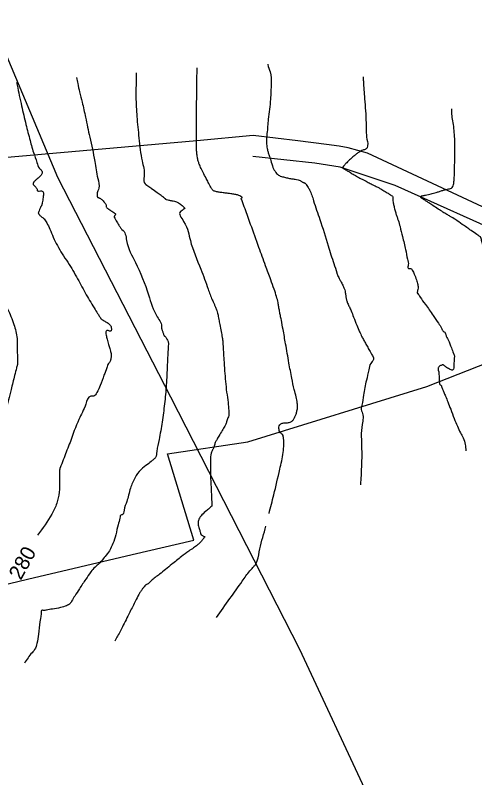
# Model space of a CAD drawing. Extents: x -478232 to -472707, y -1118753 to -1113967.
# Drawn here: x -476973 to -476849.1, y -1116433.2 to -1116227.8 of the extents above; entities that cross this region are included whole.
import ezdxf

# ---------------------------------------------------------------- set-up
doc = ezdxf.new("R2010")
doc.units = 0
for name, color, linetype in [('cestní_příkop', 7, 'Continuous'), ('ObPÚ', 7, 'Continuous'), ('plyn_vtl', 7, 'Continuous'), ('Vrstevnice_hlavni', 7, 'Continuous'), ('Vrstevnice_popis', 7, 'Continuous'), ('Vrstevnice_vedlejsi', 7, 'Continuous')]:
    doc.layers.add(name, color=color, linetype=linetype)

msp = doc.modelspace()

# ---------------------------------------------------------------- linework, layer by layer
at = {"layer": 'cestní_příkop'}
msp.add_lwpolyline([(-476811.35, -1116300.528), (-476838.09, -1116288.27), (-476870.56, -1116273.66), (-476885.39, -1116268.71), (-476892.25, -1116267.66), (-476908.96, -1116265.87)], dxfattribs=at)
at = {"layer": 'ObPÚ'}
msp.add_lwpolyline([(-477024.71, -1116392.97), (-476969.66, -1116379.77), (-476941.47, -1116373.14), (-476924.87, -1116369.24), (-476931.96, -1116345.98), (-476910.26, -1116342.76), (-476862.03, -1116327.86), (-476806.79, -1116306.12), (-476811.56, -1116301.96), (-476807.61, -1116297.99), (-476845.68, -1116280.05), (-476877.99, -1116264.97), (-476883.21, -1116263.56), (-476885.7, -1116263.12), (-476889.08, -1116262.59), (-476896.84, -1116261.69), (-476908.87, -1116260.23), (-476924.05, -1116261.64), (-477007.86, -1116269.03)], dxfattribs=at)
at = {"layer": 'plyn_vtl'}
msp.add_lwpolyline([(-476807.539, -1117641.044), (-476845.2, -1117492.76), (-476870.94, -1117395.8), (-476871.43, -1117390.49), (-476872.65, -1117388.81), (-476881.04, -1117350.81), (-476885.089, -1117338.623), (-476885.25, -1117338.15), (-476884.46, -1117337.68), (-476892.45, -1117313.5), (-476884.4, -1117251.02), (-476853.71, -1117059.16), (-476824.27, -1116852.24), (-476807.41, -1116714.75), (-476840.86, -1116589.24), (-476878.96, -1116446.19), (-476877.5, -1116438.9), (-476896.24, -1116398.66), (-476931.01, -1116330.67), (-476961.52, -1116271.51), (-476999.07, -1116182.23)], dxfattribs=at)
at = {"layer": 'Vrstevnice_hlavni'}
for points in [[(-476972.63, -1116245.946), (-476971.435, -1116251.566), (-476970.258, -1116256.657), (-476969.13, -1116261.058), (-476968.053, -1116264.769), (-476967.147, -1116267.447), (-476966.415, -1116269.092), (-476965.854, -1116269.706), (-476965.77, -1116270.372), (-476966.163, -1116271.09), (-476967.034, -1116271.861), (-476967.635, -1116272.399), (-476967.969, -1116272.704), (-476968.034, -1116272.776), (-476968.087, -1116272.882), (-476968.13, -1116273.023), (-476968.161, -1116273.199), (-476968.175, -1116273.32), (-476968.17, -1116273.387), (-476968.147, -1116273.399), (-476968.016, -1116273.533), (-476967.777, -1116273.787), (-476967.43, -1116274.162), (-476967.199, -1116274.492), (-476967.085, -1116274.778), (-476967.086, -1116275.018), (-476966.892, -1116275.155), (-476966.504, -1116275.189), (-476965.92, -1116275.119), (-476965.54, -1116275.276), (-476965.366, -1116275.659), (-476965.397, -1116276.268), (-476965.463, -1116276.912), (-476965.566, -1116277.592), (-476965.705, -1116278.307), (-476965.81, -1116278.801), (-476965.882, -1116279.074), (-476965.919, -1116279.125), (-476966.046, -1116279.376), (-476966.262, -1116279.827), (-476966.567, -1116280.478), (-476966.73, -1116280.95), (-476966.749, -1116281.244), (-476966.627, -1116281.359), (-476966.535, -1116281.459), (-476966.475, -1116281.544), (-476966.446, -1116281.615), (-476966.222, -1116281.829), (-476965.803, -1116282.187)], [(-476879.211, -1116244.407), (-476879.132, -1116245.592), (-476878.824, -1116250.292), (-476878.408, -1116256.784), (-476878.179, -1116261.185), (-476878.135, -1116263.495), (-476878.277, -1116263.715), (-476878.518, -1116263.899), (-476878.858, -1116264.049), (-476879.298, -1116264.164), (-476879.822, -1116264.41), (-476880.433, -1116264.789), (-476881.129, -1116265.3), (-476881.933, -1116265.971), (-476882.844, -1116266.803), (-476883.862, -1116267.795), (-476884.495, -1116268.498), (-476884.745, -1116268.912), (-476884.61, -1116269.036), (-476884.462, -1116269.144), (-476884.303, -1116269.235), (-476884.131, -1116269.308), (-476883.667, -1116269.572), (-476882.91, -1116270.026), (-476881.862, -1116270.671), (-476880.707, -1116271.334), (-476879.445, -1116272.016), (-476878.078, -1116272.717), (-476876.99, -1116273.267), (-476876.184, -1116273.666), (-476875.658, -1116273.914), (-476874.901, -1116274.328), (-476873.913, -1116274.908), (-476872.695, -1116275.654), (-476871.845, -1116276.183), (-476871.364, -1116276.498), (-476871.251, -1116276.596), (-476871.186, -1116276.795), (-476871.168, -1116277.096), (-476871.198, -1116277.497), (-476871.12, -1116278.154), (-476870.934, -1116279.065), (-476870.638, -1116280.231), (-476870.341, -1116281.282), (-476870.042, -1116282.216), (-476869.741, -1116283.035), (-476869.259, -1116284.766), (-476868.597, -1116287.409), (-476867.755, -1116290.964), (-476867.232, -1116293.513), (-476867.028, -1116295.056), (-476867.144, -1116295.594), (-476867.083, -1116295.931), (-476866.845, -1116296.068), (-476866.432, -1116296.004), (-476865.956, -1116296.491), (-476865.418, -1116297.531)], [(-476965.803, -1116282.187), (-476965.19, -1116282.689), (-476964.474, -1116283.762), (-476963.657, -1116285.405), (-476962.738, -1116287.619), (-476961.626, -1116289.85), (-476960.321, -1116292.1), (-476958.823, -1116294.368), (-476957.437, -1116296.61), (-476956.165, -1116298.828), (-476955.005, -1116301.02), (-476953.829, -1116303.129), (-476952.637, -1116305.157), (-476951.429, -1116307.103), (-476950.58, -1116308.471), (-476950.091, -1116309.264), (-476949.961, -1116309.479), (-476949.607, -1116309.773), (-476949.03, -1116310.146), (-476948.228, -1116310.598), (-476947.65, -1116311.009), (-476947.294, -1116311.379), (-476947.162, -1116311.709), (-476947.086, -1116312.048), (-476947.066, -1116312.396), (-476947.102, -1116312.753), (-476947.266, -1116312.934), (-476947.558, -1116312.94), (-476947.978, -1116312.77), (-476948.283, -1116312.772), (-476948.472, -1116312.946), (-476948.546, -1116313.292), (-476948.463, -1116314.009), (-476948.223, -1116315.097), (-476947.828, -1116316.556), (-476947.532, -1116317.626), (-476947.338, -1116318.306), (-476947.243, -1116318.596), (-476947.174, -1116318.794), (-476947.131, -1116318.897), (-476947.114, -1116318.907), (-476947.109, -1116319.04), (-476947.116, -1116319.297), (-476947.136, -1116319.676), (-476947.168, -1116320.033), (-476947.212, -1116320.368), (-476947.267, -1116320.681), (-476947.389, -1116321), (-476947.575, -1116321.325), (-476947.827, -1116321.655), (-476948.324, -1116322.808), (-476949.065, -1116324.783), (-476950.05, -1116327.579), (-476950.973, -1116329.458), (-476951.834, -1116330.417), (-476952.633, -1116330.458), (-476953.964, -1116332.55), (-476955.828, -1116336.693), (-476958.224, -1116342.886), (-476959.84, -1116347.053), (-476960.675, -1116349.192), (-476960.73, -1116349.304), (-476960.777, -1116349.408), (-476960.816, -1116349.503), (-476960.847, -1116349.589), (-476960.873, -1116349.661), (-476960.896, -1116349.72), (-476960.914, -1116349.764), (-476960.936, -1116349.838), (-476960.964, -1116349.94), (-476960.997, -1116350.072), (-476961.035, -1116351.178), (-476961.078, -1116353.26), (-476961.127, -1116356.316), (-476961.804, -1116359.297), (-476963.11, -1116362.202), (-476966.98, -1116367.86)], [(-476865.418, -1116297.531), (-476864.818, -1116299.122), (-476864.467, -1116300.395), (-476864.365, -1116301.351), (-476864.512, -1116301.988), (-476864.592, -1116302.428), (-476864.606, -1116302.671), (-476864.555, -1116302.715), (-476863.826, -1116303.734), (-476862.422, -1116305.725), (-476860.341, -1116308.69), (-476858.889, -1116310.813), (-476858.066, -1116312.093), (-476857.871, -1116312.53), (-476857.682, -1116312.843), (-476857.501, -1116313.032), (-476857.326, -1116313.098), (-476856.919, -1116313.847), (-476856.278, -1116315.281), (-476855.405, -1116317.4), (-476854.838, -1116318.911), (-476854.579, -1116319.815), (-476854.628, -1116320.112), (-476854.67, -1116320.658), (-476854.707, -1116321.453), (-476854.737, -1116322.497), (-476854.881, -1116323.162), (-476855.138, -1116323.449), (-476855.509, -1116323.357), (-476855.938, -1116323.164), (-476856.426, -1116322.872), (-476856.971, -1116322.48), (-476857.361, -1116322.205), (-476857.596, -1116322.046), (-476857.676, -1116322.003), (-476857.858, -1116322.032), (-476858.141, -1116322.132), (-476858.525, -1116322.304), (-476858.789, -1116322.535), (-476858.93, -1116322.826), (-476858.951, -1116323.175), (-476858.941, -1116323.447), (-476858.899, -1116323.641), (-476858.826, -1116323.758), (-476858.772, -1116324.202), (-476858.735, -1116324.973), (-476858.717, -1116326.071), (-476858.64, -1116326.845), (-476858.505, -1116327.293), (-476858.311, -1116327.415), (-476858.163, -1116327.578), (-476858.059, -1116327.78), (-476858.001, -1116328.022), (-476857.804, -1116328.545), (-476857.469, -1116329.349), (-476856.995, -1116330.435), (-476856.371, -1116331.98), (-476855.597, -1116333.982), (-476854.673, -1116336.443), (-476853.798, -1116338.548), (-476852.972, -1116340.296), (-476852.196, -1116341.688), (-476851.702, -1116343.416), (-476851.505, -1116345.19)]]:
    msp.add_spline(points, degree=3, dxfattribs=at)
at = {"layer": 'Vrstevnice_vedlejsi'}
for points in [[(-476904.914, -1116240.956), (-476904.89, -1116241.085), (-476904.249, -1116243.09), (-476904.014, -1116246.212), (-476904.185, -1116250.452), (-476904.762, -1116255.809), (-476905.118, -1116259.678), (-476905.254, -1116262.056), (-476905.168, -1116262.946), (-476905.07, -1116263.677), (-476904.959, -1116264.251), (-476904.834, -1116264.667), (-476904.55, -1116265.565), (-476904.105, -1116266.946), (-476903.499, -1116268.809), (-476902.727, -1116270.168), (-476901.787, -1116271.024), (-476900.681, -1116271.376), (-476899.604, -1116271.651), (-476898.556, -1116271.851), (-476897.537, -1116271.973), (-476896.757, -1116272.127), (-476896.217, -1116272.313), (-476895.916, -1116272.529), (-476895.673, -1116272.691), (-476895.488, -1116272.798), (-476895.36, -1116272.851), (-476895.212, -1116272.911), (-476895.044, -1116272.98), (-476894.854, -1116273.057), (-476894.559, -1116273.393), (-476894.157, -1116273.988), (-476893.648, -1116274.842), (-476892.557, -1116277.782), (-476890.883, -1116282.807), (-476888.627, -1116289.917), (-476887.101, -1116294.731), (-476886.305, -1116297.25), (-476886.24, -1116297.472), (-476886.154, -1116297.704), (-476886.049, -1116297.946), (-476885.924, -1116298.198), (-476885.658, -1116298.715), (-476885.252, -1116299.498), (-476884.705, -1116300.547), (-476884.309, -1116301.443), (-476884.065, -1116302.186), (-476883.973, -1116302.776), (-476883.901, -1116303.26), (-476883.848, -1116303.638), (-476883.814, -1116303.911), (-476883.753, -1116304.225), (-476883.664, -1116304.581), (-476883.547, -1116304.979), (-476883.382, -1116305.416), (-476883.168, -1116305.892), (-476882.905, -1116306.409), (-476882.443, -1116307.481), (-476881.78, -1116309.11), (-476880.918, -1116311.295), (-476880.168, -1116313.074), (-476879.529, -1116314.446)], [(-476940.363, -1116243.311), (-476940.391, -1116244.9), (-476940.445, -1116249.8), (-476940.197, -1116255.129), (-476939.646, -1116260.887), (-476938.792, -1116267.074), (-476938.217, -1116271.203), (-476937.92, -1116273.273), (-476937.901, -1116273.286), (-476937.868, -1116273.307), (-476937.822, -1116273.338), (-476937.762, -1116273.377), (-476937.226, -1116273.761), (-476936.213, -1116274.49), (-476934.723, -1116275.563), (-476933.674, -1116276.328), (-476933.066, -1116276.787), (-476932.898, -1116276.938), (-476932.767, -1116277.05), (-476932.672, -1116277.125), (-476932.614, -1116277.161), (-476932.561, -1116277.212), (-476932.514, -1116277.276), (-476932.471, -1116277.353), (-476932.166, -1116277.462), (-476931.6, -1116277.6), (-476930.771, -1116277.77), (-476930.088, -1116277.936), (-476929.55, -1116278.098), (-476929.157, -1116278.257), (-476928.715, -1116278.515), (-476928.224, -1116278.874), (-476927.684, -1116279.332), (-476927.373, -1116279.664), (-476927.293, -1116279.87), (-476927.443, -1116279.95), (-476927.592, -1116280.05), (-476927.739, -1116280.17), (-476927.886, -1116280.311), (-476928.047, -1116280.446), (-476928.222, -1116280.575), (-476928.412, -1116280.699), (-476927.598, -1116283.353), (-476925.779, -1116288.539), (-476922.956, -1116296.256), (-476920.986, -1116301.579), (-476919.868, -1116304.506), (-476919.603, -1116305.039), (-476919.315, -1116305.698), (-476919.005, -1116306.485), (-476918.672, -1116307.399), (-476918.437, -1116308.111), (-476918.298, -1116308.623), (-476918.257, -1116308.935), (-476918.103, -1116309.773), (-476917.836, -1116311.138), (-476917.456, -1116313.03), (-476917.186, -1116314.607), (-476917.025, -1116315.869), (-476916.974, -1116316.816), (-476916.879, -1116318.417), (-476916.739, -1116320.672), (-476916.553, -1116323.58), (-476916.304, -1116326.468), (-476915.992, -1116329.336), (-476915.616, -1116332.182), (-476915.434, -1116334.292), (-476915.446, -1116335.664), (-476915.653, -1116336.3), (-476915.834, -1116336.857), (-476915.992, -1116337.337), (-476916.124, -1116337.739), (-476916.52, -1116338.514), (-476917.179, -1116339.661)], [(-476920.024, -1116274.609), (-476920.191, -1116274.284), (-476920.605, -1116273.493), (-476921.265, -1116272.236), (-476922.172, -1116270.513), (-476922.876, -1116269.082), (-476923.377, -1116267.944), (-476923.674, -1116267.1), (-476923.897, -1116266.106), (-476924.047, -1116264.962), (-476924.123, -1116263.67), (-476924.146, -1116260.322), (-476924.116, -1116254.919), (-476924.032, -1116247.459), (-476923.965, -1116242.11), (-476923.963, -1116241.972)], [(-476956.448, -1116244.625), (-476956.133, -1116246.216), (-476955.632, -1116248.439), (-476954.954, -1116251.244), (-476954.047, -1116255.302), (-476952.912, -1116260.614), (-476951.549, -1116267.178), (-476950.725, -1116271.786), (-476950.44, -1116274.437), (-476950.693, -1116275.131), (-476950.86, -1116275.622), (-476950.94, -1116275.91), (-476950.934, -1116275.995), (-476950.924, -1116276.132), (-476950.911, -1116276.32), (-476950.895, -1116276.558), (-476950.826, -1116276.742), (-476950.705, -1116276.87), (-476950.531, -1116276.943), (-476950.346, -1116277.03), (-476950.15, -1116277.131), (-476949.942, -1116277.247), (-476949.659, -1116277.483), (-476949.3, -1116277.839), (-476948.865, -1116278.314), (-476948.584, -1116278.717), (-476948.455, -1116279.05), (-476948.48, -1116279.311), (-476948.387, -1116279.56), (-476948.176, -1116279.798), (-476947.848, -1116280.025), (-476947.629, -1116280.176), (-476947.52, -1116280.252), (-476947.337, -1116280.372), (-476946.972, -1116280.613), (-476946.425, -1116280.973), (-476946.083, -1116281.255), (-476945.948, -1116281.459), (-476946.019, -1116281.585), (-476946.101, -1116281.715), (-476946.195, -1116281.847), (-476946.3, -1116281.982), (-476946.149, -1116282.441), (-476945.74, -1116283.222), (-476945.075, -1116284.326), (-476944.599, -1116285.081), (-476944.311, -1116285.486), (-476944.212, -1116285.541), (-476942.971, -1116288.509), (-476940.587, -1116294.389), (-476937.06, -1116303.181), (-476934.711, -1116309.06), (-476933.539, -1116312.027), (-476933.545, -1116312.081), (-476933.515, -1116312.225), (-476933.451, -1116312.458), (-476933.352, -1116312.78), (-476933.242, -1116313.116), (-476933.12, -1116313.468), (-476932.986, -1116313.834), (-476932.854, -1116314.103), (-476932.724, -1116314.275), (-476932.595, -1116314.35), (-476932.424, -1116314.552), (-476932.211, -1116314.88), (-476931.956, -1116315.335), (-476931.788, -1116315.745), (-476931.706, -1116316.108), (-476931.712, -1116316.426), (-476931.809, -1116318.414), (-476931.999, -1116322.071)], [(-476989.604, -1116247.757), (-476987.96, -1116255.508), (-476986.825, -1116260.993), (-476986.201, -1116264.211), (-476986.087, -1116265.16), (-476985.806, -1116266.774), (-476985.356, -1116269.054), (-476984.737, -1116271.999), (-476984.398, -1116274.084), (-476984.338, -1116275.309), (-476984.556, -1116275.675), (-476984.69, -1116276.117), (-476984.739, -1116276.637), (-476984.702, -1116277.233), (-476984.73, -1116277.766), (-476984.82, -1116278.235), (-476984.975, -1116278.639), (-476985.069, -1116278.965), (-476985.103, -1116279.21), (-476985.077, -1116279.376), (-476985.031, -1116279.821), (-476984.966, -1116280.544), (-476984.881, -1116281.545), (-476984.842, -1116282.23), (-476984.85, -1116282.599), (-476984.904, -1116282.652), (-476984.922, -1116282.71), (-476984.905, -1116282.772), (-476984.851, -1116282.839), (-476984.813, -1116282.889), (-476984.791, -1116282.921), (-476984.784, -1116282.936), (-476984.743, -1116283.07), (-476984.666, -1116283.322), (-476984.554, -1116283.694), (-476983.992, -1116285.452), (-476982.98, -1116288.597), (-476981.517, -1116293.129), (-476979.709, -1116297.695), (-476977.554, -1116302.295), (-476975.053, -1116306.93), (-476973.368, -1116311.127), (-476972.498, -1116314.886), (-476972.442, -1116318.208), (-476972.403, -1116320.462), (-476972.379, -1116321.649), (-476972.371, -1116321.769), (-476972.381, -1116321.889), (-476972.411, -1116322.01), (-476972.46, -1116322.131), (-476972.515, -1116322.301), (-476972.576, -1116322.52), (-476972.642, -1116322.788), (-476973.161, -1116324.836), (-476974.131, -1116328.665), (-476975.552, -1116334.273), (-476976.975, -1116339.456), (-476978.399, -1116344.212)], [(-476862.167, -1116277.885), (-476862.516, -1116277.66), (-476862.88, -1116277.419), (-476863.261, -1116277.164), (-476863.658, -1116276.893), (-476863.644, -1116276.65), (-476863.219, -1116276.437), (-476862.383, -1116276.252), (-476861.608, -1116276.074), (-476860.895, -1116275.901), (-476860.242, -1116275.735), (-476859.495, -1116275.528), (-476858.653, -1116275.282), (-476857.716, -1116274.996), (-476856.902, -1116274.767), (-476856.21, -1116274.595), (-476855.64, -1116274.48), (-476855.212, -1116274.192), (-476854.924, -1116273.733), (-476854.778, -1116273.101), (-476854.667, -1116272.111), (-476854.59, -1116270.764), (-476854.547, -1116269.059), (-476854.514, -1116267.078), (-476854.491, -1116264.821), (-476854.478, -1116262.288), (-476854.578, -1116259.934), (-476854.79, -1116257.76), (-476855.115, -1116255.766), (-476855.291, -1116254.085), (-476855.319, -1116252.999)], [(-476904.561, -1116362.036), (-476903.277, -1116356.987), (-476901.654, -1116350.127), (-476900.754, -1116345.616), (-476900.577, -1116343.455), (-476900.638, -1116341.852), (-476900.937, -1116340.805), (-476901.473, -1116340.315), (-476901.795, -1116339.754), (-476901.902, -1116339.124), (-476901.796, -1116338.424), (-476901.368, -1116337.935), (-476900.62, -1116337.658), (-476899.55, -1116337.593), (-476898.702, -1116337.335), (-476898.076, -1116336.882), (-476897.672, -1116336.235), (-476897.343, -1116335.474), (-476897.088, -1116334.6), (-476896.908, -1116333.611), (-476896.963, -1116332.294), (-476897.254, -1116330.647), (-476897.78, -1116328.672), (-476898.43, -1116325.624), (-476899.203, -1116321.504), (-476900.099, -1116316.311), (-476900.782, -1116312.454), (-476901.251, -1116309.932), (-476901.507, -1116308.746), (-476901.737, -1116307.567), (-476901.942, -1116306.396), (-476902.122, -1116305.234), (-476902.545, -1116303.624), (-476903.212, -1116301.566), (-476904.122, -1116299.061), (-476905.478, -1116295.324), (-476907.28, -1116290.356), (-476909.527, -1116284.156), (-476911.043, -1116279.97), (-476911.829, -1116277.798), (-476911.885, -1116277.641), (-476911.946, -1116277.501), (-476912.012, -1116277.38), (-476912.084, -1116277.277), (-476912.068, -1116277.175), (-476911.965, -1116277.074), (-476911.774, -1116276.973), (-476911.835, -1116276.82), (-476912.148, -1116276.613), (-476912.713, -1116276.354), (-476913.522, -1116276.128), (-476914.576, -1116275.933), (-476915.874, -1116275.772), (-476916.92, -1116275.64), (-476917.714, -1116275.54), (-476918.256, -1116275.47), (-476918.735, -1116275.371), (-476919.151, -1116275.244), (-476919.503, -1116275.089), (-476919.794, -1116274.877), (-476920.024, -1116274.609)], [(-476830.004, -1116337.192), (-476830.024, -1116337.111), (-476830.41, -1116335.428), (-476830.827, -1116333.32), (-476831.274, -1116330.788), (-476831.771, -1116328.654), (-476832.316, -1116326.918), (-476832.911, -1116325.58), (-476833.334, -1116324.596), (-476833.587, -1116323.965), (-476833.67, -1116323.688), (-476834.318, -1116323.131), (-476835.532, -1116322.296), (-476837.312, -1116321.181), (-476838.547, -1116320.358), (-476839.236, -1116319.827), (-476839.38, -1116319.587), (-476839.494, -1116319.368), (-476839.579, -1116319.17), (-476839.634, -1116318.992), (-476840.075, -1116316.67), (-476840.902, -1116312.202), (-476842.113, -1116305.588), (-476843.009, -1116300.799), (-476843.589, -1116297.835), (-476843.852, -1116296.695), (-476844.029, -1116295.777), (-476844.118, -1116295.081), (-476844.12, -1116294.606), (-476844.356, -1116294.145), (-476844.825, -1116293.698), (-476845.528, -1116293.265), (-476845.999, -1116292.954), (-476846.238, -1116292.763), (-476846.245, -1116292.694), (-476846.381, -1116292.101), (-476846.647, -1116290.985), (-476847.042, -1116289.346), (-476847.31, -1116288.244), (-476847.451, -1116287.68), (-476847.465, -1116287.653), (-476847.492, -1116287.622), (-476847.531, -1116287.586), (-476847.582, -1116287.545), (-476847.628, -1116287.511), (-476847.669, -1116287.482), (-476847.704, -1116287.46), (-476848.514, -1116286.896), (-476850.101, -1116285.792), (-476852.464, -1116284.147), (-476854.338, -1116282.883), (-476855.723, -1116281.999), (-476856.62, -1116281.495), (-476857.695, -1116280.839), (-476858.95, -1116280.031), (-476860.385, -1116279.07), (-476861.457, -1116278.355), (-476862.167, -1116277.885)], [(-476879.529, -1116314.446), (-476879.002, -1116315.411), (-476878.427, -1116316.447), (-476877.805, -1116317.555), (-476877.136, -1116318.733), (-476876.674, -1116319.598), (-476876.419, -1116320.148), (-476876.372, -1116320.383), (-476876.477, -1116320.714), (-476876.735, -1116321.139), (-476877.146, -1116321.659), (-476877.674, -1116323.331), (-476878.319, -1116326.155), (-476879.081, -1116330.131), (-476879.531, -1116332.884), (-476879.67, -1116334.415), (-476879.498, -1116334.724), (-476879.476, -1116338.08), (-476879.605, -1116344.484), (-476879.883, -1116353.935), (-476879.901, -1116354.294)], [(-476931.999, -1116322.071), (-476932.281, -1116327.399), (-476932.746, -1116332.515), (-476933.394, -1116337.42), (-476934.225, -1116342.114), (-476934.828, -1116345.306), (-476935.202, -1116346.998), (-476935.348, -1116347.189), (-476936.055, -1116347.793), (-476937.322, -1116348.81), (-476939.15, -1116350.241), (-476940.691, -1116352.385), (-476941.945, -1116355.244), (-476942.913, -1116358.818), (-476943.642, -1116361.196), (-476944.132, -1116362.379), (-476944.383, -1116362.368), (-476944.756, -1116363.267), (-476945.251, -1116365.076), (-476945.868, -1116367.796), (-476946.656, -1116370.126), (-476947.615, -1116372.064), (-476948.746, -1116373.612), (-476949.765, -1116374.864), (-476950.675, -1116375.82), (-476951.474, -1116376.479), (-476952.576, -1116377.787), (-476953.98, -1116379.743), (-476955.687, -1116382.347), (-476956.954, -1116384.309), (-476957.78, -1116385.627), (-476958.166, -1116386.301), (-476959.162, -1116386.889), (-476960.767, -1116387.389), (-476962.981, -1116387.802), (-476964.549, -1116388.052), (-476965.471, -1116388.14), (-476965.746, -1116388.065), (-476966.043, -1116389.11), (-476966.36, -1116391.274), (-476966.7, -1116394.557), (-476967.164, -1116397.033), (-476967.755, -1116398.702), (-476968.471, -1116399.563), (-476970.508, -1116402.39)], [(-476917.179, -1116339.661), (-476918.1, -1116341.181), (-476918.757, -1116342.351), (-476919.149, -1116343.171), (-476919.275, -1116343.64), (-476919.488, -1116344.231), (-476919.787, -1116344.942), (-476920.174, -1116345.774), (-476920.367, -1116347.803), (-476920.368, -1116351.028), (-476920.174, -1116355.45), (-476920.046, -1116358.408), (-476919.981, -1116359.903), (-476919.98, -1116359.935), (-476919.981, -1116359.961), (-476919.981, -1116359.983), (-476919.983, -1116359.998), (-476919.984, -1116360.012), (-476919.984, -1116360.025), (-476919.984, -1116360.036), (-476919.99, -1116360.048), (-476920, -1116360.062), (-476920.015, -1116360.078), (-476920.466, -1116360.475), (-476921.351, -1116361.253), (-476922.672, -1116362.412), (-476923.452, -1116363.61), (-476923.691, -1116364.847), (-476923.389, -1116366.124), (-476923.149, -1116367.034), (-476922.972, -1116367.577), (-476922.857, -1116367.754), (-476922.672, -1116367.918), (-476922.417, -1116368.068), (-476922.091, -1116368.205), (-476921.908, -1116368.311), (-476921.868, -1116368.386), (-476921.972, -1116368.43), (-476922.078, -1116368.527), (-476922.188, -1116368.677), (-476922.3, -1116368.88), (-476922.508, -1116369.165), (-476922.813, -1116369.534), (-476923.214, -1116369.984), (-476923.913, -1116370.577), (-476924.909, -1116371.31), (-476926.203, -1116372.185), (-476928.167, -1116373.663), (-476930.801, -1116375.744), (-476934.105, -1116378.428), (-476936.327, -1116380.223), (-476937.466, -1116381.128), (-476937.524, -1116381.145), (-476937.646, -1116381.225), (-476937.834, -1116381.37), (-476938.086, -1116381.578), (-476938.428, -1116381.982), (-476938.859, -1116382.58), (-476939.378, -1116383.373), (-476940.386, -1116385.237), (-476941.881, -1116388.172), (-476943.863, -1116392.179), (-476945.404, -1116395.064), (-476946.181, -1116396.434)], [(-476918.727, -1116390.089), (-476915.118, -1116384.955), (-476911.783, -1116380.288), (-476909.727, -1116377.518), (-476908.948, -1116376.643), (-476908.407, -1116376.02), (-476908.103, -1116375.648), (-476908.037, -1116375.528), (-476907.21, -1116372.378), (-476905.624, -1116366.197), (-476905.433, -1116365.452)]]:
    msp.add_spline(points, degree=3, dxfattribs=at)

# ---------------------------------------------------------------- texts
at = {"layer": 'Vrstevnice_popis'}
msp.add_text(' 280 ', height=4, rotation=61.23008, dxfattribs=at).set_placement((-476972.2, -1116381.516))

doc.saveas('drawing.dxf')
